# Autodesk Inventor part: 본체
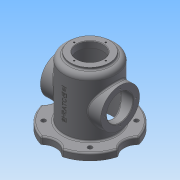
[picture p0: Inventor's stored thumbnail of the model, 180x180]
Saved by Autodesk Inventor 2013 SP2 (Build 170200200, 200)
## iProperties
Created: 2026-07
Part Number: 본체
Material: Generic
Document SubType Name: Modeling
Designer: a
Density: 1 g/cm^3
Author: a
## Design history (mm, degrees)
sketch "스케치1"
  geometry: L1 (100, 0)-(-100, 0); L2 (0, -100)-(0, 100); A1 r 30 centre (100, 0) between (79.12, -21.541) and (79.12, 21.541); A2 r 30 centre (0, 100) between (-21.541, 79.12) and (21.541, 79.12); A3 r 30 centre (-100, 0) between (-79.12, -21.541) and (-79.12, 21.541); A4 r 30 centre (0, -100) between (21.541, -79.12) and (-21.541, -79.12); A5 r 82 centre (0, 0) between (21.541, -79.12) and (79.12, -21.541); A6 r 82 centre (0, 0) between (-79.12, -21.541) and (-21.541, -79.12); A7 r 82 centre (0, 0) between (79.12, 21.541) and (21.541, 79.12); A8 r 82 centre (0, 0) between (-21.541, 79.12) and (-79.12, 21.541); 3 further points
  constraints: 16 point on circle, 8 centre point, 4 coincident, 4 end point, 4 midpoint, 1 horizontal, 1 perpendicular, 9 other
  dimensions: "d1" = 200 distance of L1.start L1.end; "d2" = 200 distance of L2.start L2.end; "d3" = 60 diameter of A1; "d6" = 360 deg dimension on A5.centre A1.centre (derived); "d8" = 82 radius of A5; "d9" = 82 radius of A6; "d10" = 82 radius of A8; "d11" = 82 radius of A7
extrude "돌출1" new body sketch "스케치1" distance "d12" = 14; taper "d13" = 0 deg
sketch "스케치2"
  geometry: C1 r 53 at (0, 0); 1 further point
  constraints: 1 centre point, 1 coincident
  dimensions: "d14" = 106 diameter of C1
extrude "돌출2" join sketch "스케치2" distance "d15" = 132; taper "d16" = 0 deg
sketch "스케치3"
  geometry: C1 r 53 at (0, 0) reference; C2 r 40 at (0, 0)
  constraints: 1 centre point, 1 coincident
  dimensions: "d17" = 80 diameter of C2
extrude "돌출3" join sketch "스케치3" distance "d18" = 5; taper "d19" = 0 deg
sketch "스케치4"
  geometry: L1 (-70, 0)-(-70, 14) reference; L2 (-70, 14)-(-53, 14) reference; L3 (-53, 14)-(-53, 132) reference; L4 (-53, 132)-(-40, 132) reference; L5 (-40, 132)-(-40, 137) reference; L6 (-40, 137)-(40, 137) reference; L7 (40, 137)-(40, 132) reference; L8 (40, 132)-(53, 132) reference; L9 (53, 132)-(53, 14) reference; L10 (53, 14)-(70, 14) reference; L11 (70, 14)-(70, 0) reference; L12 (70, 0)-(-70, 0) reference; L13 (-62, 68)-(62, 68); L14 (-62, 68)-(-62, 108); L15 (-62, 108)-(62, 108); L16 (62, 108)-(62, 68); 3 further points
  constraints: 8 end point, 2 midpoint, 2 parallel, 2 perpendicular, 1 vertical alignment
  dimensions: "d20" = 68 distance from line of point (0, 0) L13; "d21" = 124 distance of L13.start L13.end; "d22" = 80 diameter of L15 L13
revolve "회전1" sketch "스케치4" stored, may be unused: angle "d23" = 90 deg
sketch "스케치5"
  geometry: L1 (-70, 0)-(-70, 14) reference; L2 (-70, 14)-(-53, 14) reference; L3 (-53, 14)-(-53, 28) reference; L4 (-53, 28)-(-62, 28) reference; L5 (-62, 28)-(-62, 108) reference; L6 (-62, 108)-(-53, 108) reference; L7 (-53, 108)-(-53, 132) reference; L8 (-53, 132)-(-40, 132) reference; L9 (-40, 132)-(-40, 137) reference; L10 (-40, 137)-(40, 137) reference; L11 (40, 137)-(40, 132) reference; L12 (40, 132)-(53, 132) reference; L13 (53, 132)-(53, 108) reference; L14 (53, 108)-(62, 108) reference; L15 (62, 108)-(62, 28) reference; L16 (62, 28)-(53, 28) reference; L17 (53, 28)-(53, 14) reference; L18 (53, 14)-(70, 14) reference; L19 (70, 14)-(70, 0) reference; L20 (70, 0)-(-70, 0) reference; L21 (0, 0)-(0, 137); L22 (-27, 137)-(-27, 124); L23 (-27, 124)-(-42, 124); L24 (-45, 121)-(-45, 0); L25 (-27, 137)-(0, 137); L26 (-45, 0)-(0, 0); A1 r 3 centre (-42, 121) between (-42, 124) and (-45, 121)
  constraints: 12 end point, 2 perpendicular, 2 point on circle, 2 point on line, 2 tangent, 1 centre point, 1 collinear, 1 midpoint, 1 parallel, 1 vertical
  dimensions: "d24" = 54 diameter of L22 L21; "d26" = 90 diameter of L24 L21; "d27" = 124 distance between parallel lines of L20 L23; "d28" = 3 radius of A1
revolve "회전2" sketch "스케치5" stored, may be unused: angle "d29" = 90 deg
chamfer "모따기1" distance "d30" = 1; stored, may be unused: second distance "d31" = 2, angle "d32" = 45 deg
sketch "스케치6"
  geometry: L1 (70, 14)-(70, 0) reference; L2 (70, 0)-(45, 0) reference; L3 (45, 0)-(45, 121) reference; L4 (42, 124)-(27, 124) reference; L5 (27, 124)-(27, 136) reference; L6 (27, 136)-(28, 137) reference; L7 (28, 137)-(40, 137) reference; L8 (40, 137)-(40, 132) reference; L9 (40, 132)-(53, 132) reference; L10 (53, 132)-(53, 108) reference; L11 (53, 108)-(62, 108) reference; L12 (62, 108)-(62, 28) reference; L13 (62, 28)-(53, 28) reference; L14 (53, 28)-(53, 14) reference; L15 (53, 14)-(70, 14) reference; L16 (-70, 0)-(-70, 14) reference; L17 (-70, 14)-(-53, 14) reference; L18 (-53, 14)-(-53, 28) reference; L19 (-53, 28)-(-62, 28) reference; L20 (-62, 28)-(-62, 108) reference; L21 (-62, 108)-(-53, 108) reference; L22 (-53, 108)-(-53, 132) reference; L23 (-53, 132)-(-40, 132) reference; L24 (-40, 132)-(-40, 137) reference; L25 (-40, 137)-(-28, 137) reference; L26 (-28, 137)-(-27, 136) reference; L27 (-27, 136)-(-27, 124) reference; L28 (-27, 124)-(-42, 124) reference; L29 (-45, 121)-(-45, 0) reference; L30 (-45, 0)-(-70, 0) reference; L31 (-62, 68)-(62, 68); L32 (-62, 68)-(-62, 95); L33 (-62, 95)-(62, 95); L34 (62, 95)-(62, 68); A1 r 3 centre (42, 121) between (45, 121) and (42, 124) reference; A2 r 3 centre (-42, 121) between (-42, 124) and (-45, 121) reference; 1 further point
  constraints: 8 end point, 2 midpoint, 2 point on line, 1 collinear, 1 perpendicular
  dimensions: "d33" = 54 diameter of L33 L31
revolve "회전3" sketch "스케치6" stored, may be unused: angle "d34" = 90 deg
fillet "모깎기1" dims "d35" = 3
fillet "모깎기2" dims "d36" = 10
sketch "스케치7" dims "d37" = 135
  geometry: L1 (0, 0)-(-92.353, 92.353); L2 (0, 0)-(0, 100); L3 (0, 0)-(92.353, 92.353); L4 (-100, 0)-(100, 0); C1 r 53 at (0, 0) reference; C2 r 45 at (0, 0) reference; C3 r 4.5 at (-47.73, 47.73); C4 r 4.5 at (47.73, 47.73); C5 r 4.5 at (-47.73, -47.73); C6 r 4.5 at (47.73, -47.73); A1 r 82 centre (0, 0) between (-21.541, 79.12) and (-79.12, 21.541) reference; A2 r 30 centre (0, 100) between (-21.541, 79.12) and (21.541, 79.12) reference; A3 r 82 centre (0, 0) between (79.12, 21.541) and (21.541, 79.12) reference; A4 r 30 centre (100, 0) between (79.12, 21.541) and (79.12, -21.541) reference; A5 r 82 centre (0, 0) between (21.541, -79.12) and (79.12, -21.541) reference; A6 r 30 centre (0, -100) between (21.541, -79.12) and (-21.541, -79.12) reference; A7 r 82 centre (0, 0) between (-79.12, -21.541) and (-21.541, -79.12) reference; A8 r 30 centre (-100, 0) between (-79.12, -21.541) and (-79.12, 21.541) reference
  constraints: 8 end point, 4 centre point, 4 symmetric about line, 1 coincident, 1 perpendicular, 1 point on line, 1 vertical, 6 other
  dimensions: "d38" = 45 deg angle of L2 L1; "d40" = 9 diameter of C3
extrude "돌출4" cut sketch "스케치7" stored distance "d41" = 5; taper "d42" = 0 deg
chamfer "모따기2" distance "d43" = 1; stored, may be unused: second distance "d44" = 2, angle "d45" = 45 deg
sketch "스케치8" dims "d46" = 65
  geometry: L1 (0, 0)-(0, 32.5); C1 r 28 at (0, 0) reference; C2 r 40 at (0, 0) reference; 4 further points
  constraints: 2 coincident, 2 end point, 1 vertical, 1 vertical alignment, 7 other
  dimensions: "d49" = 360 deg dimension on L1.start point (0, 32.5) (derived)
hole "구멍1" sketch "스케치8" at (0, 32.5), (-32.5, 0), (0, -32.5), (32.5, 0) diameter "d51" = 3.242; stored, may be unused: countersink angle "d55" = 90 deg, drill point angle "d57" = 118 deg; dims "d52" = 8, "d53" = 4, "d54" = 2, "d56" = 10
sketch "스케치9" dims "d58" = 65
  geometry: L1 (-53.666, -68)-(-53.666, -54) reference; L2 (-53.666, -54)-(53.666, -54) reference; L3 (53.666, -54)-(53.666, -68) reference; L4 (53.666, -68)-(-53.666, -68) reference; L5 (0, 0)-(0, 32.5); C1 r 28 at (0, 0) reference; C2 r 40 at (0, 0) reference; 5 further points
  constraints: 2 coincident, 2 end point, 1 perpendicular, 1 vertical alignment, 7 other
  dimensions: "d61" = 360 deg dimension on L5.start point (0, 32.5) (derived)
hole "구멍2" sketch "스케치9" at (0, 32.5), (-32.5, 0), (0, -32.5), (32.5, 0) diameter "d63" = 3.242; stored, may be unused: countersink angle "d67" = 90 deg, drill point angle "d69" = 118 deg; dims "d64" = 8, "d65" = 4, "d66" = 2, "d68" = 10
node "작업 평면1"
sketch "스케치10"
  geometry: L1 (-21.541, 0)-(21.541, 0) reference; 3 further points
  constraints: 1 midpoint, 1 vertical alignment, 1 other
  dimensions: "d70" = 70 distance of point (0, 0) point (0, 70)
feature "엠보싱1" sketch "스케치10" dims "d1" = 200, "d2" = 200, "d3" = 60, "d6" = 360 deg (derived), "d8" = 82, "d9" = 82, "d10" = 82, "d11" = 82, "d71" = 0.5, "d72" = 0
fillet "모깎기3" dims "d73" = 3
fillet "모깎기4" dims "d74" = 3
fillet "모깎기5" dims "d75" = 3
fillet "모깎기6" dims "d76" = 3
fillet "모깎기7" dims "d77" = 3
node "솔리드1"
mirror "대칭1"
node "절단 모서리 투영1"
node "절단 모서리 투영2"
node "절단 모서리 투영3"
node "절단 모서리 투영4"
node "절단 모서리 투영5"
node "절단 모서리 투영6"
other parameters: "d0" = 164
